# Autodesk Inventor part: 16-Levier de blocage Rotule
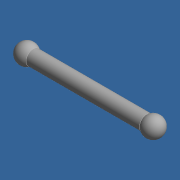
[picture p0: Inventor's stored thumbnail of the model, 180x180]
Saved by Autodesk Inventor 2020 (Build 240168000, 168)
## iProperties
Created: 2022-03
Part Number: 16-Levier de blocage Rotule
Material: Générique
Document SubType Name: Modeling
Designer: %USERNAME%
Density: 1 g/cm^3
Appearance: Par défaut
Author: %USERNAME%
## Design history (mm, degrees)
sketch "Esquisse2"
  geometry: L1 (-30, 3)-(30, 3); L2 (30, 3)-(30, 0); L3 (30, 0)-(-30, 0); L4 (-30, 0)-(-30, 3); A1 r 4 centre (-26, 0) between (-22, 0) and (-30, 0); A2 r 4 centre (26, 0) between (30, 0) and (22, 0); 4 further points
  constraints: 8 end point, 4 point on circle, 4 point on line, 2 centre point, 2 parallel, 1 coincident, 1 equal radius, 1 horizontal, 1 midpoint, 1 perpendicular
  dimensions: "d0" = 6 diameter of L1 L3; "d1" = 60 distance of L1.start L1.end; "d2" = 8 diameter of A1
revolve "Révolution1" sketch "Esquisse2" stored, may be unused: angle "d3" = 90 deg
node "Solide1"
